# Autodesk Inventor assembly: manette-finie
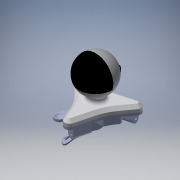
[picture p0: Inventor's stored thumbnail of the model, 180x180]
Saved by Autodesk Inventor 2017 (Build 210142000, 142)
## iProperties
Created: 2013-10
Part Number: manette-finie
Material: Générique
Document SubType Name: Assembly
Designer: Bruno
Sending System: SolidWorks 2013
Last Author: christophe
Last Saved: 2014-02-15
Author: Bruno
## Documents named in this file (4)
- D:\Cours\1-Cours-2018-19\1Ssi\7- EDC-mvt\Haptique-2017\Reel-Inventor\manette-finie.iam
- D:\Cours\1-Cours-2018-19\1Ssi\7- EDC-mvt\Haptique-2017\Reel-Inventor\manette.iam
- D:\Cours\1-Cours-2018-19\1Ssi\7- EDC-mvt\Haptique-2017\Reel-Inventor\manette2.ipt
- D:\Cours\Systèmes\SI\Robot Haptique\Documentations_pedagogique\Modèle solidworks\Reel-Inventor\BASE.ipt
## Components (3 placed, 3 different names)
1. manette:1 [sub-assembly] — Affleurement:1, Placage:1, Placage:2
2. manette2:1
3. BASE:1 — Affleurement:1, Placage:1, Placage:2
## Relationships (3: Mate 2, Flush 1)
- Affleurement:1 [Flush]: manette:1 ↔ BASE:1
- Placage:1 [Mate]: manette:1 ↔ BASE:1
- Placage:2 [Mate]: manette:1 ↔ BASE:1
